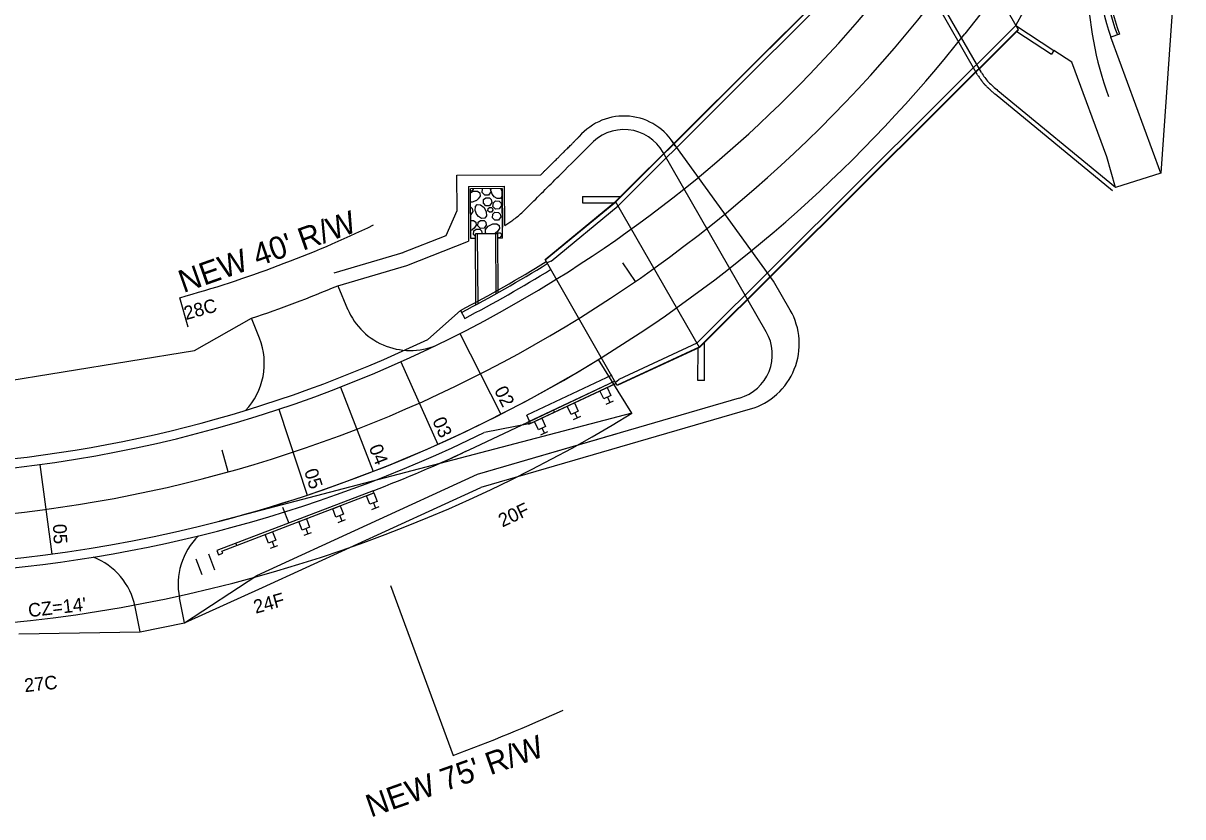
# Model space of a CAD drawing. Extents: x 126 to 1541327, y 13613 to 1200627.
# Drawn here: x 1539946.5 to 1540203.2, y 1199311.3 to 1199486.8 of the extents above; entities that cross this region are included whole.
import ezdxf

# ---------------------------------------------------------------- set-up
doc = ezdxf.new("R2010")
doc.units = 0
for name, color, linetype in [('BR_CONCRETE', 7, 'Continuous'), ('BR_PROPOSED_TRAVELWAY', 7, 'Continuous'), ('RD_HC_Cl', 7, 'Continuous'), ('RD_HC_Data_Tic', 7, 'Continuous'), ('RD_PD_ALT1_TX', 7, 'Continuous'), ('RD_PD_BOC', 7, 'Continuous'), ('RD_PD_CstnLmt', 7, 'Continuous'), ('RD_PD_CstnLmt_TX', 7, 'Continuous'), ('RD_PD_DR_ErosCtrl', 7, 'Continuous'), ('RD_PD_DR_Inlet', 7, 'Continuous'), ('RD_PD_Driveway', 7, 'Continuous'), ('RD_PD_EOP', 7, 'Continuous'), ('RD_PD_Final_TrvlWay', 7, 'Continuous'), ('RD_PD_FOC', 7, 'Continuous'), ('RD_PD_GR', 7, 'Continuous'), ('RD_PD_PaveShd', 7, 'Continuous'), ('RD_PD_RW', 7, 'Continuous'), ('RD_Sketch1', 7, 'Continuous'), ('RD_Sketch8', 7, 'Continuous')]:
    doc.layers.add(name, color=color, linetype=linetype)

# ---------------------------------------------------------------- blocks, each defined once
blk = doc.blocks.new('Guardrail_MTBBC2_Transition')
at = {"layer": 'RD_PD_GR'}
for p, q in [((3.875, 3.75), (2.125, 3.75)), ((3, 2.5), (3, 3.75)), ((11.875, 3.75), (10.125, 3.75)), ((11, 2.5), (11, 3.75)), ((19.875, 3.75), (18.125, 3.75)), ((19, 2.5), (19, 3.75)), ((0, 0.5), (0, 0)), ((21.25, 0.5), (0, 0.5)), ((0, 0), (21.25, 0)), ((2.125, 0.5), (2.125, 2.5)), ((2.125, 2.5), (3.875, 2.5)), ((3.875, 0.5), (2.125, 0.5)), ((3.875, 2.5), (3.875, 0.5)), ((10.125, 0.5), (10.125, 2.5)), ((10.125, 2.5), (11.875, 2.5)), ((11.875, 0.5), (10.125, 0.5)), ((11.875, 2.5), (11.875, 0.5)), ((15, 0.5), (15, 0)), ((18.125, 0.5), (18.125, 2.5)), ((18.125, 2.5), (19.875, 2.5)), ((19.875, 0.5), (18.125, 0.5)), ((19.875, 2.5), (19.875, 0.5)), ((21.25, 0), (21.25, 0.5))]:
    blk.add_line(p, q, dxfattribs=at)
blk = doc.blocks.new('Guardrail_MT2_Leading_with_Buffer')
at = {"layer": 'RD_PD_GR'}
for p, q in [((25.51, 5.13), (23.76, 5.04)), ((38.94, 2.11), (38.74, 5.85)), ((41.94, 2.27), (41.74, 6.01)), ((1.55, 3.84), (-0.2, 3.74)), ((-0.13, 2.5), (1.61, 2.59)), ((0.74, 2.54), (0.67, 3.79)), ((1.61, 2.59), (1.72, 0.59)), ((9.53, 4.27), (7.79, 4.18)), ((7.85, 2.93), (9.6, 3.02)), ((7.96, 0.93), (7.85, 2.93)), ((8.73, 2.98), (8.66, 4.22)), ((9.6, 3.02), (9.71, 1.03)), ((17.52, 4.7), (15.77, 4.61)), ((15.84, 3.36), (17.59, 3.45)), ((15.95, 1.36), (15.84, 3.36)), ((16.72, 3.41), (16.65, 4.66)), ((17.59, 3.45), (17.7, 1.46)), ((23.83, 3.79), (25.58, 3.89)), ((23.94, 1.79), (23.83, 3.79)), ((24.7, 3.84), (24.64, 5.09)), ((25.58, 3.89), (25.69, 1.89)), ((36.89, 3), (35.89, 2.94)), ((35.89, 2.94), (35.92, 2.44)), ((36.95, 2), (36.89, 3)), ((-0.03, 0.5), (-0.13, 2.5)), ((35.92, 2.44), (-0.03, 0.5)), ((1.72, 0.59), (-0.03, 0.5)), ((-0.03, 0.5), (0, 0)), ((0, 0), (36.95, 2)), ((9.71, 1.03), (7.96, 0.93)), ((17.7, 1.46), (15.95, 1.36)), ((20.17, -2.67), (19.97, 1.08)), ((25.69, 1.89), (23.94, 1.79)), ((32.43, 2.25), (32.45, 1.75))]:
    blk.add_line(p, q, dxfattribs=at)

msp = doc.modelspace()

# ---------------------------------------------------------------- linework, layer by layer
at = {"layer": 'BR_CONCRETE'}
for p, q in [((1540077.64, 1199447.44), (1540148.21, 1199517.71)), ((1540077.68, 1199447.36), (1540148.25, 1199517.64)), ((1540078.2, 1199446.47), (1540148.77, 1199516.74)), ((1540166.77, 1199485.39), (1540148.21, 1199517.71)), ((1540166.22, 1199486.37), (1540176.63, 1199505.52)), ((1540095.64, 1199416.09), (1540166.22, 1199486.37)), ((1540096.16, 1199415.2), (1540166.73, 1199485.47)), ((1540096.2, 1199415.12), (1540166.77, 1199485.39)), ((1540166.22, 1199486.37), (1540174.66, 1199480.84)), ((1540166.42, 1199485.04), (1540174.11, 1199480)), ((1540174.66, 1199480.84), (1540174.11, 1199480)), ((1540062.02, 1199434.56), (1540077.64, 1199447.44)), ((1540062.07, 1199434.49), (1540077.68, 1199447.36)), ((1540070.32, 1199448.55), (1540070.31, 1199447.13)), ((1540070.31, 1199447.13), (1540077.25, 1199447.12)), ((1540070.32, 1199448.55), (1540078.74, 1199448.53)), ((1540096.2, 1199415.12), (1540077.64, 1199447.44)), ((1540063.35, 1199434.25), (1540078.2, 1199446.47)), ((1540078.02, 1199406.71), (1540062.02, 1199434.56)), ((1540063.35, 1199434.25), (1540062.45, 1199433.83)), ((1540095.64, 1199416.09), (1540078.39, 1199408.08)), ((1540097.29, 1199407.8), (1540097.3, 1199416.22)), ((1540096.16, 1199415.2), (1540077.98, 1199406.78)), ((1540096.2, 1199415.12), (1540078.02, 1199406.71)), ((1540095.87, 1199407.8), (1540095.88, 1199414.94)), ((1540077.61, 1199407.44), (1540078.39, 1199408.08)), ((1540097.29, 1199407.8), (1540095.87, 1199407.8))]:
    msp.add_line(p, q, dxfattribs=at)
at = {"layer": 'BR_PROPOSED_TRAVELWAY'}
msp.add_line((1540174.48, 1199509.25), (1540154.92, 1199484.5), dxfattribs=at)
for radius, start in [(290, 301.8034), (310, 301.6792)]:
    msp.add_arc((1539911.68, 1199676.68), radius, start, 321.687, dxfattribs=at)
at = {"layer": 'RD_HC_Cl'}
msp.add_arc((1539911.68, 1199676.68), 300, 272.8619, 321.687, dxfattribs=at)
at = {"layer": 'RD_HC_Data_Tic'}
for p, q in [((1540082.05, 1199429.75), (1540079.22, 1199433.87)), ((1539991.88, 1199387.6), (1539990.55, 1199392.42))]:
    msp.add_line(p, q, dxfattribs=at)
at = {"layer": 'RD_PD_ALT1_TX'}
for p, q in [((1540043.18, 1199418.21), (1540052.25, 1199400.38)), ((1540030.1, 1199411.96), (1540038.27, 1199393.7)), ((1540016.72, 1199406.37), (1540023.96, 1199387.73)), ((1540003.08, 1199401.46), (1540009.38, 1199382.48)), ((1539950.22, 1199389.25), (1539952.88, 1199369.43))]:
    msp.add_line(p, q, dxfattribs=at)
at = {"layer": 'RD_PD_BOC'}
for p, q in [((1540189.14, 1199484.42), (1540187.27, 1199483.73)), ((1540077.7, 1199407.2), (1540058.84, 1199398.34))]:
    msp.add_line(p, q, dxfattribs=at)
for centre, radius, start, end in [((1540234.21, 1199500.96), 48, 141.687, 200.1561), ((1539911.68, 1199676.68), 285.5, 297.4563, 301.8338)]:
    msp.add_arc(centre, radius, start, end, dxfattribs=at)
at = {"layer": 'RD_PD_CstnLmt'}
for p, q in [((1540203.17, 1199523.55), (1540198.31, 1199453.66)), ((1540158.58, 1199475.93), (1540138.18, 1199511.5)), ((1540188.28, 1199450.52), (1540162.25, 1199471.89)), ((1540110.97, 1199418.61), (1540088.2, 1199458.25)), ((1540045.05, 1199450.73), (1540053.04, 1199450.77)), ((1540045.05, 1199450.73), (1540045.11, 1199438.67)), ((1540045.61, 1199439.23), (1540045.55, 1199450.23)), ((1540052.55, 1199450.27), (1540052.6, 1199441.77)), ((1540053.09, 1199442.1), (1540053.04, 1199450.77)), ((1540046.55, 1199439.23), (1540045.61, 1199439.23)), ((1540031.46, 1199433.25), (1540045.11, 1199438.67)), ((1540016.16, 1199428.77), (1540031.46, 1199433.25)), ((1539984.44, 1199414.44), (1539997.05, 1199421.59)), ((1539939.79, 1199407.26), (1539984.44, 1199414.44)), ((1540047.06, 1199387.09), (1540105.07, 1199403.96)), ((1540047.06, 1199387.09), (1540077.73, 1199396.01)), ((1539998.22, 1199364.74), (1540047.06, 1199387.09)), ((1539982.23, 1199354.27), (1539998.22, 1199364.74)), ((1539945.58, 1199351.83), (1539972.43, 1199352.28))]:
    msp.add_line(p, q, dxfattribs=at)
for centre, radius, start, end in [((1540079.49, 1199453.31), 10.01, 29.556, 139.5224), ((1540102.31, 1199413.59), 10.02, 285.9823, 30.0801)]:
    msp.add_arc(centre, radius, start, end, dxfattribs=at)
for points in [[(1540158.58, 1199475.93), (1540159.36, 1199474.81), (1540160.18, 1199473.82), (1540161.14, 1199472.91), (1540162.25, 1199471.89)], [(1540053.09, 1199442.1), (1540054.89, 1199443.3), (1540055.9, 1199444.06), (1540056.86, 1199444.9), (1540057.78, 1199445.79), (1540058.68, 1199446.69), (1540065.5, 1199453.47), (1540071.87, 1199459.81)]]:
    msp.add_spline(points, degree=3, dxfattribs=at)
at = {"layer": 'RD_PD_DR_ErosCtrl'}
for p, q in [((1540157.72, 1199475.43), (1540137.31, 1199511)), ((1540187.64, 1199449.75), (1540161.61, 1199471.12)), ((1540112.6, 1199429.82), (1540090.02, 1199460.95)), ((1540042.53, 1199453.21), (1540061.09, 1199453.32)), ((1540042.58, 1199445.4), (1540042.53, 1199453.21)), ((1540040.11, 1199439.91), (1540042.58, 1199445.4)), ((1540030.35, 1199436.04), (1540040.11, 1199439.91)), ((1540015.32, 1199431.65), (1540030.61, 1199436.13)), ((1540116.29, 1199423.41), (1540112.6, 1199429.82)), ((1540047.9, 1199384.21), (1540107.47, 1199401.53)), ((1539999.47, 1199362.02), (1540047.82, 1199384.14)), ((1539982.23, 1199354.27), (1539999.47, 1199362.02))]:
    msp.add_line(p, q, dxfattribs=at)
for centre, radius, start, end in [((1540079.49, 1199453.31), 13.01, 29.556, 139.5224), ((1540103.28, 1199415.94), 15, 286.2163, 29.8783)]:
    msp.add_arc(centre, radius, start, end, dxfattribs=at)
for points, degree in [([(1540157.76, 1199475.36), (1540157.89, 1199475.17), (1540158.09, 1199474.89), (1540158.32, 1199474.56), (1540158.43, 1199474.4), (1540158.49, 1199474.32), (1540158.52, 1199474.28), (1540158.53, 1199474.26), (1540158.54, 1199474.25), (1540158.54, 1199474.24), (1540158.54, 1199474.24), (1540158.54, 1199474.24), (1540158.54, 1199474.24), (1540158.54, 1199474.24), (1540158.54, 1199474.24), (1540158.62, 1199474.14), (1540158.69, 1199474.03), (1540158.85, 1199473.83), (1540158.93, 1199473.73), (1540159.09, 1199473.52), (1540159.18, 1199473.42), (1540159.32, 1199473.27), (1540159.37, 1199473.22), (1540159.43, 1199473.16), (1540159.44, 1199473.15), (1540159.47, 1199473.12), (1540159.48, 1199473.11), (1540159.48, 1199473.11), (1540159.48, 1199473.11), (1540159.48, 1199473.11), (1540159.48, 1199473.11), (1540159.48, 1199473.11), (1540159.48, 1199473.11), (1540159.49, 1199473.11), (1540159.51, 1199473.08), (1540159.53, 1199473.06), (1540159.72, 1199472.88), (1540159.89, 1199472.72), (1540160.14, 1199472.48), (1540160.23, 1199472.4), (1540160.35, 1199472.28), (1540160.4, 1199472.24), (1540160.44, 1199472.2), (1540160.45, 1199472.19), (1540160.46, 1199472.18), (1540160.46, 1199472.18), (1540160.47, 1199472.18), (1540160.47, 1199472.18), (1540160.47, 1199472.18), (1540160.48, 1199472.17), (1540160.51, 1199472.14), (1540160.88, 1199471.8), (1540161.24, 1199471.47), (1540161.57, 1199471.16)], 3), ([(1540061.09, 1199453.32), (1540063.98, 1199456.19), (1540066.87, 1199459.06), (1540069.76, 1199461.94)], 2)]:
    msp.add_open_spline(points, degree=degree, dxfattribs=at)
at = {"layer": 'RD_PD_DR_Inlet'}
for p, q in [((1540052.55, 1199450.27), (1540045.55, 1199450.23)), ((1540045.61, 1199439.23), (1540045.55, 1199450.23)), ((1540046.1, 1199450.23), (1540046.12, 1199450.14)), ((1540052.61, 1199439.27), (1540052.55, 1199450.27)), ((1540046.04, 1199445.2), (1540045.58, 1199444.55)), ((1540045.94, 1199441.14), (1540045.6, 1199441)), ((1540046.61, 1199439.23), (1540045.61, 1199439.23)), ((1540051.6, 1199440.26), (1540046.6, 1199440.23)), ((1540046.69, 1199424.55), (1540046.6, 1199440.23)), ((1540047.19, 1199424.82), (1540047.1, 1199440.24)), ((1540048.08, 1199440.3), (1540048.04, 1199440.24)), ((1540051.07, 1199440.41), (1540050.69, 1199440.26)), ((1540051.18, 1199427.01), (1540051.1, 1199440.26)), ((1540051.68, 1199427.29), (1540051.6, 1199440.26)), ((1540052.61, 1199439.27), (1540051.61, 1199439.26))]:
    msp.add_line(p, q, dxfattribs=at)
for points in [[(1540046.12, 1199450.14), (1540045.82, 1199449.7), (1540045.55, 1199449.69)], [(1540045.55, 1199449.36), (1540046.19, 1199449.69), (1540047.1, 1199449.71), (1540047.61, 1199449.35), (1540047.67, 1199448.62), (1540047.25, 1199447.97), (1540046.78, 1199447.59)], [(1540050, 1199449.57), (1540049.5, 1199448.85), (1540048.69, 1199448.8), (1540048.13, 1199449.38), (1540048.2, 1199450.19), (1540048.27, 1199450.24)], [(1540049.81, 1199450.25), (1540049.87, 1199450.19), (1540050, 1199449.57)], [(1540050.43, 1199448.91), (1540050.05, 1199449.85), (1540050.08, 1199450.25)], [(1540052.13, 1199450.27), (1540052.5, 1199449.54), (1540052.52, 1199448.63), (1540052.16, 1199448.11), (1540051.44, 1199448.06), (1540050.79, 1199448.47), (1540050.4, 1199448.95)], [(1540046.82, 1199447.61), (1540045.88, 1199447.23), (1540045.56, 1199447.26)], [(1540050.23, 1199447.21), (1540049.73, 1199446.49), (1540048.93, 1199446.44), (1540048.37, 1199447.02), (1540048.44, 1199447.83), (1540048.94, 1199448.25), (1540049.73, 1199448.19), (1540050.11, 1199447.83), (1540050.23, 1199447.21)], [(1540052.37, 1199446.51), (1540051.87, 1199445.79), (1540051.06, 1199445.74), (1540050.5, 1199446.32), (1540050.58, 1199447.13), (1540051.07, 1199447.55), (1540051.87, 1199447.49), (1540052.24, 1199447.13), (1540052.37, 1199446.51)], [(1540045.57, 1199446.15), (1540045.91, 1199445.83), (1540046.04, 1199445.2)], [(1540046.95, 1199444.5), (1540046.57, 1199445.44), (1540046.64, 1199446.3), (1540047.03, 1199446.72), (1540047.73, 1199446.71), (1540048.53, 1199446.09), (1540049.02, 1199445.12), (1540049.04, 1199444.21), (1540048.68, 1199443.7), (1540047.95, 1199443.65), (1540047.3, 1199444.06), (1540046.92, 1199444.53)], [(1540050.5, 1199445.48), (1540050.2, 1199445.05), (1540049.72, 1199445.02), (1540049.38, 1199445.36), (1540049.43, 1199445.85), (1540049.72, 1199446.1), (1540050.2, 1199446.07), (1540050.43, 1199445.85), (1540050.5, 1199445.48)], [(1540052.24, 1199444.02), (1540051.74, 1199443.3), (1540050.94, 1199443.25), (1540050.37, 1199443.83), (1540050.45, 1199444.64), (1540050.94, 1199445.06), (1540051.74, 1199445), (1540052.12, 1199444.64), (1540052.24, 1199444.02)], [(1540045.59, 1199443.22), (1540046.22, 1199443.24), (1540046.73, 1199442.87), (1540046.79, 1199442.15), (1540046.37, 1199441.5), (1540045.9, 1199441.12)], [(1540049.02, 1199442.2), (1540048.52, 1199441.48), (1540047.71, 1199441.43), (1540047.15, 1199442.01), (1540047.23, 1199442.82), (1540047.72, 1199443.24), (1540048.52, 1199443.18), (1540048.89, 1199442.82), (1540049.02, 1199442.2)], [(1540049.1, 1199440.25), (1540048.84, 1199440.49), (1540048.85, 1199441.19), (1540049.47, 1199441.99), (1540050.44, 1199442.48), (1540051.35, 1199442.5), (1540051.86, 1199442.14), (1540051.92, 1199441.42), (1540051.5, 1199440.77), (1540051.03, 1199440.38)], [(1540046.61, 1199439.7), (1540046.21, 1199440.1), (1540046.29, 1199440.92), (1540046.78, 1199441.33), (1540047.58, 1199441.28), (1540047.95, 1199440.92), (1540048.08, 1199440.3)], [(1540051.33, 1199440.26), (1540051.6, 1199440.48), (1540052.08, 1199440.45), (1540052.3, 1199440.24), (1540052.38, 1199439.86)], [(1540052.38, 1199439.86), (1540052.08, 1199439.43), (1540051.61, 1199439.4)]]:
    msp.add_lwpolyline(points, dxfattribs=at)
at = {"layer": 'RD_PD_Driveway'}
for p, q in [((1540198.31, 1199453.66), (1540187.27, 1199483.73)), ((1540178.63, 1199478.24), (1540174.66, 1199480.84)), ((1540186.32, 1199457.31), (1540178.63, 1199478.24)), ((1540188.28, 1199450.52), (1540186.32, 1199457.31)), ((1540198.31, 1199453.66), (1540188.28, 1199450.52)), ((1540016.15, 1199428.8), (1540018.33, 1199423.64)), ((1539998.82, 1199417.18), (1539997.05, 1199421.59)), ((1539982.23, 1199354.27), (1539981.11, 1199359.78)), ((1539972.43, 1199352.28), (1539971.31, 1199357.79)), ((1539972.43, 1199352.28), (1539982.23, 1199354.27))]:
    msp.add_line(p, q, dxfattribs=at)
for centre, radius, start, end in [((1539911.68, 1199676.68), 269, 288.5032, 292.8527), ((1540032.15, 1199429.47), 15, 202.8527, 295.9794), ((1539984.89, 1199411.6), 15, 316.1357, 21.8033), ((1539995.81, 1199362.76), 15, 134.2625, 191.4743), ((1539956.61, 1199354.8), 15, 11.4743, 68.6862)]:
    msp.add_arc(centre, radius, start, end, dxfattribs=at)
at = {"layer": 'RD_PD_EOP'}
for p, q in [((1540043.32, 1199423.34), (1540044.24, 1199421.57)), ((1540076.84, 1199409.01), (1540057.99, 1199400.15)), ((1540058.84, 1199398.34), (1540057.99, 1199400.15))]:
    msp.add_line(p, q, dxfattribs=at)
for centre, radius, start, end in [((1540234.21, 1199500.96), 50, 141.687, 200.1561), ((1539911.68, 1199676.68), 287.5, 297.4565, 301.8202)]:
    msp.add_arc(centre, radius, start, end, dxfattribs=at)
at = {"layer": 'RD_PD_Final_TrvlWay'}
for radius, end in [(290, 301.8034), (310, 301.6792)]:
    msp.add_arc((1539911.68, 1199676.68), radius, 272.8619, end, dxfattribs=at)
at = {"layer": 'RD_PD_FOC'}
msp.add_line((1540077.48, 1199407.65), (1540058.63, 1199398.79), dxfattribs=at)
for centre, radius, start, end in [((1540234.21, 1199500.96), 48.5, 141.687, 200.1561), ((1539911.68, 1199676.68), 286, 297.4563, 301.8303)]:
    msp.add_arc(centre, radius, start, end, dxfattribs=at)
at = {"layer": 'RD_PD_GR'}
msp.add_line((1540045.24, 1199392.5), (1540058.25, 1199398.61), dxfattribs=at)
for start in [290.9523, 293.7998]:
    msp.add_arc((1539911.68, 1199676.68), 314, start, 295.1711, dxfattribs=at)
at = {"layer": 'RD_PD_PaveShd'}
for p, q in [((1540043.32, 1199423.34), (1540036.08, 1199416.93)), ((1540058.84, 1199398.34), (1540048.59, 1199396.32))]:
    msp.add_line(p, q, dxfattribs=at)
for radius, end in [(288, 295.5911), (312, 296.0265)]:
    msp.add_arc((1539911.68, 1199676.68), radius, 272.8619, end, dxfattribs=at)
at = {"layer": 'RD_PD_RW'}
for p, q in [((1539983.01, 1199419.59), (1539981.19, 1199426.14)), ((1540027.79, 1199362.47), (1540041.66, 1199324.93))]:
    msp.add_line(p, q, dxfattribs=at)
for radius, start, end in [(260, 285.5054, 295.6117), (375, 290.28, 294.3056)]:
    msp.add_arc((1539911.68, 1199676.68), radius, start, end, dxfattribs=at)
at = {"layer": 'RD_Sketch1'}
msp.add_arc((1540258.69, 1199497.05), 76.64, 181.1834, 200.1561, dxfattribs=at)
at = {"layer": 'RD_Sketch8'}
for q in [(1540073.89, 1199412.5), (1539990.06, 1199376.75)]:
    msp.add_line((1540081.21, 1199400.57), q, dxfattribs=at)
for radius, start in [(310, 284.6446), (324, 272.8619)]:
    msp.add_arc((1539911.68, 1199676.68), radius, start, 301.5493, dxfattribs=at)

# ---------------------------------------------------------------- block references
at = {"layer": 'RD_PD_GR'}
for name, p, rotation in [('Guardrail_MTBBC2_Transition', (1540077.48, 1199407.65), -154.8289364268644), ('Guardrail_MT2_Leading_with_Buffer', (1540023.97, 1199383.44), -162.1417156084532)]:
    msp.add_blockref(name, p, dxfattribs=dict(at, rotation=rotation))

# ---------------------------------------------------------------- texts
at = {"layer": 'RD_PD_ALT1_TX'}
for s, rotation, p in [('02', 296.9645, (1540050.69, 1199405.66)), ('03', 294.0997, (1540037.01, 1199398.95)), ('04', 291.235, (1540022.98, 1199393.03)), ('05', 288.3702, (1540008.67, 1199387.79)), ('05', 272.8619, (1539953.11, 1199376.05))]:
    msp.add_text(s, height=3, rotation=rotation, dxfattribs=at).set_placement(p)
at = {"layer": 'RD_PD_CstnLmt_TX'}
for s, rotation, p in [('28C', 15.5054, (1539982.57, 1199421.18)), ('20F', 25.0547, (1540052.57, 1199375.31)), ('24F', 15.5054, (1539997.98, 1199356.24)), ('27C', 5.9561, (1539946.92, 1199338.9))]:
    msp.add_text(s, height=3, rotation=rotation, dxfattribs=at).set_placement(p)
at = {"layer": 'RD_PD_RW'}
for s, p in [("NEW 40' R/W", (1539981.99, 1199427.16)), ("NEW 75' R/W", (1540023.46, 1199311.17))]:
    msp.add_text(s, height=5, rotation=19.4514, dxfattribs=at).set_placement(p)
at = {"layer": 'RD_Sketch8'}
msp.add_text("CZ=14'", height=3, rotation=6.498, dxfattribs=at).set_placement((1539947.8, 1199355.48))

doc.saveas('drawing.dxf')
